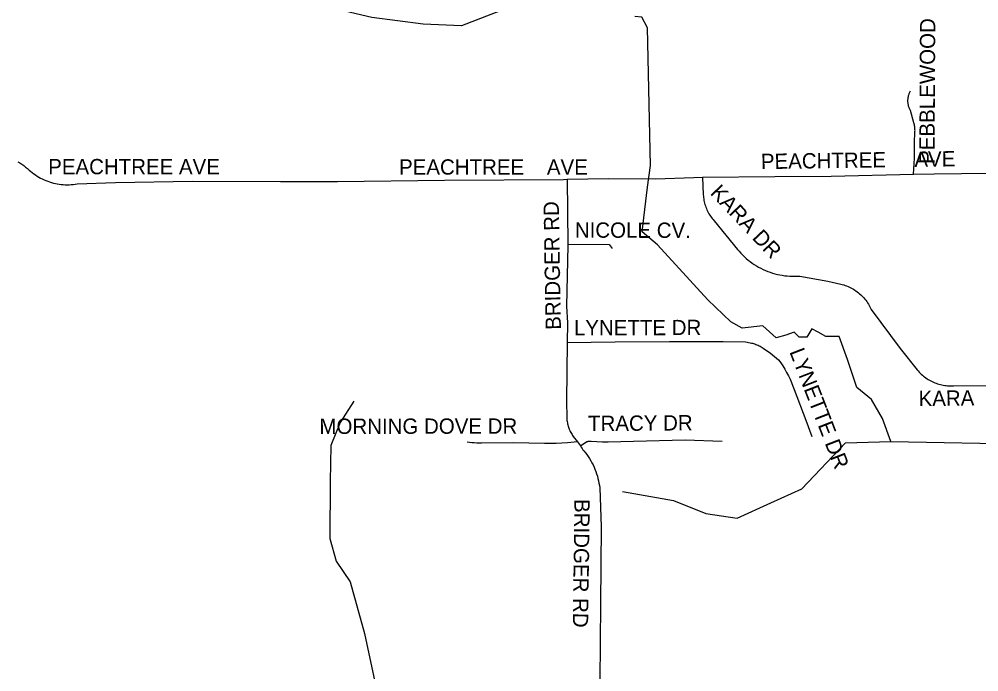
# Model space of a CAD drawing. Extents: x 1670563 to 1761545, y 515755 to 578944.
# Drawn here: x 1715137 to 1719841, y 561545 to 564740 of the extents above; entities that cross this region are included whole.
import ezdxf

# ---------------------------------------------------------------- set-up
doc = ezdxf.new("R2010")
doc.units = 0
for name, color, linetype in [('SHP_LINE', 7, 'Continuous'), ('STREETCL', 7, 'Continuous'), ('STRNAMES', 7, 'Continuous')]:
    doc.layers.add(name, color=color, linetype=linetype)

msp = doc.modelspace()

# ---------------------------------------------------------------- linework, layer by layer
at = {"layer": 'SHP_LINE'}
for points in [[(1717837, 564821), (1717716, 564791), (1717521, 564791), (1717305, 564708), (1717117, 564715), (1716866, 564749), (1716622, 564805), (1716344, 564944), (1716072, 565069), (1715870, 565195), (1715773, 565264), (1715752, 565410), (1715738, 565605), (1715689, 565710)], [(1718190, 563699), (1718216, 563918), (1718231, 564024), (1718216, 564697), (1718189, 564750), (1718155, 564753)], [(1719410, 562672), (1719369, 562785), (1719314, 562878), (1719242, 562936), (1719197, 563073), (1719156, 563186), (1719091, 563186), (1719053, 563207), (1719022, 563224), (1718998, 563183), (1718960, 563183), (1718936, 563207), (1718895, 563193), (1718847, 563180), (1718782, 563238), (1718681, 563227), (1718626, 563259), (1718512, 563366), (1718266, 563635), (1718190, 563699)], [(1716777, 562870), (1716710, 562766), (1716665, 562653), (1716662, 562476), (1716660, 562197), (1716691, 562087), (1716760, 561985), (1716829, 561733), (1716881, 561495)], [(1718095, 562428), (1718344, 562383), (1718502, 562319), (1718657, 562297), (1718822, 562372), (1718973, 562440), (1719187, 562665), (1719410, 562672)], [(1719410, 562672), (1720107, 562660)]]:
    msp.add_lwpolyline(points, dxfattribs=at)
at = {"layer": 'STREETCL'}
for points in [[(1719520.3, 563981), (1719525.1, 564059.7), (1719525.1, 564086.8), (1719525.7, 564135.8), (1719527.7, 564184.8), (1719527.8, 564189.6), (1719527.9, 564194.5), (1719527.7, 564199.3), (1719527.4, 564204.1), (1719527, 564208.9), (1719526.4, 564213.7), (1719525.7, 564218.5), (1719524.8, 564223.2), (1719523.7, 564227.9), (1719522.5, 564232.6), (1719505.7, 564293.2), (1719504.1, 564296.1), (1719502.7, 564299.1), (1719501.3, 564302.1), (1719500, 564305.2), (1719498.9, 564308.3), (1719497.8, 564311.5), (1719496.8, 564314.6), (1719496, 564317.9), (1719495.3, 564321.1), (1719494.7, 564324.4), (1719494.2, 564327.7), (1719493.8, 564331), (1719493.5, 564334.3), (1719493.3, 564337.6), (1719493.2, 564340.9), (1719493.3, 564344.2), (1719493.5, 564347.6), (1719493.8, 564350.9), (1719494.2, 564354.2), (1719494.7, 564357.5), (1719495.3, 564360.7), (1719496, 564364), (1719496.8, 564367.2), (1719497.8, 564370.4), (1719498.9, 564373.5), (1719500, 564376.6), (1719501.3, 564379.7), (1719502.7, 564382.7), (1719504.1, 564385.7), (1719505.7, 564388.7)], [(1715130.6, 564041.9), (1715140.4, 564036), (1715149.9, 564029.7), (1715159.2, 564023.2), (1715168.3, 564016.3), (1715177.2, 564009.1), (1715185.8, 564001.6), (1715193.1, 563995.2), (1715200.7, 563989.1), (1715208.5, 563983.2), (1715216.5, 563977.6), (1715224.7, 563972.3), (1715233, 563967.2), (1715241.6, 563962.5), (1715250.2, 563958.1), (1715259.1, 563953.9), (1715268, 563950.1), (1715277.1, 563946.6), (1715286.4, 563943.3), (1715295.7, 563940.5), (1715305.1, 563937.9), (1715314.6, 563935.7), (1715324.2, 563933.8), (1715333.8, 563932.2), (1715343.5, 563931), (1715353.2, 563930.1), (1715362.9, 563929.5), (1715372.7, 563929.3), (1715382.4, 563929.4), (1715392.2, 563929.9), (1715401.9, 563930.7), (1715411.6, 563931.8), (1715421.2, 563933.3), (1715609.1, 563940.5), (1715986.4, 563947.8), (1716417.4, 563945.4), (1716696.8, 563945.4), (1717222.6, 563952.7), (1717805.3, 563955.8), (1717822.3, 563956.1)], [(1718486.5, 563966.1), (1718841.6, 563970.4), (1719116.2, 563972), (1719520.3, 563981)], [(1719520.3, 563981), (1719621.9, 563983.3), (1720157.1, 563989.8)], [(1717822.3, 563956.1), (1718026.1, 563959.8), (1718255.7, 563959.1), (1718444.3, 563965.5), (1718486.5, 563966.1)], [(1717822.3, 563956.1), (1717826.1, 563638.5)], [(1718486.5, 563966.1), (1718490.3, 563880.8), (1718490.7, 563873.7), (1718491.4, 563866.7), (1718492.3, 563859.7), (1718493.5, 563852.8), (1718494.9, 563845.9), (1718496.6, 563839), (1718498.5, 563832.3), (1718500.6, 563825.5), (1718503, 563818.9), (1718505.6, 563812.4), (1718508.4, 563805.9), (1718511.5, 563799.5), (1718514.7, 563793.3), (1718518.2, 563787.2), (1718521.9, 563781.2), (1718525.8, 563775.3), (1718529.9, 563769.6), (1718534.2, 563764), (1718538.7, 563758.6), (1718543.4, 563753.3), (1718657.7, 563613), (1718665.7, 563603.6), (1718674, 563594.4), (1718682.6, 563585.5), (1718691.5, 563577), (1718700.7, 563568.7), (1718710.1, 563560.8), (1718719.9, 563553.2), (1718729.9, 563545.9), (1718740.1, 563539), (1718750.6, 563532.4), (1718761.3, 563526.3), (1718772.2, 563520.4), (1718783.3, 563515), (1718794.6, 563510), (1718806.1, 563505.3), (1718817.7, 563501.1), (1718829.4, 563497.2), (1718841.3, 563493.8), (1718853.3, 563490.8), (1718865.3, 563488.2), (1718877.5, 563486), (1718889.7, 563484.2), (1718902, 563482.9), (1718914.4, 563481.9), (1718926.7, 563481.5), (1718939.1, 563481.4), (1718951.4, 563481.8), (1718963.7, 563482.6), (1719100.5, 563457.6), (1719164.2, 563442.7), (1719171.4, 563440.9), (1719178.6, 563438.8), (1719185.6, 563436.5), (1719192.6, 563433.9), (1719199.5, 563431.1), (1719206.3, 563428.1), (1719213, 563424.9), (1719219.6, 563421.4), (1719226, 563417.7), (1719232.4, 563413.7), (1719238.6, 563409.6), (1719244.6, 563405.3), (1719250.5, 563400.7), (1719256.2, 563396), (1719261.8, 563391), (1719267.2, 563385.9), (1719272.4, 563380.6), (1719277.4, 563375.1), (1719282.2, 563369.4), (1719286.9, 563363.6), (1719291.3, 563357.6), (1719295.6, 563351.5), (1719299.6, 563345.3), (1719303.4, 563338.9), (1719307, 563332.3), (1719310.3, 563325.7), (1719313.5, 563318.9), (1719455.4, 563127.5), (1719539.3, 563023.2), (1719543.8, 563017.7), (1719548.6, 563012.3), (1719553.6, 563007.1), (1719558.7, 563002.1), (1719564, 562997.3), (1719569.5, 562992.6), (1719575.1, 562988.2), (1719580.9, 562983.9), (1719586.8, 562979.9), (1719592.8, 562976), (1719599, 562972.3), (1719605.3, 562968.9), (1719611.7, 562965.7), (1719618.2, 562962.7), (1719624.9, 562959.9), (1719631.6, 562957.4), (1719638.4, 562955.1), (1719645.2, 562953), (1719652.2, 562951.2), (1719659.2, 562949.6), (1719666.2, 562948.2), (1719673.3, 562947.1), (1719680.4, 562946.3), (1719687.6, 562945.6), (1719694.7, 562945.3), (1719701.9, 562945.1), (1719709.1, 562945.3), (1719716.2, 562945.6), (1720086.9, 562948.2)], [(1717826.1, 563638.5), (1717826.2, 563632.7), (1717819.9, 563334.3), (1717824.1, 563253.1), (1717823, 563156.5)], [(1717826.1, 563638.5), (1718029.2, 563637.2), (1718043.6, 563617.7)], [(1717823, 563156.5), (1717819.9, 562872.1), (1717821.3, 562786.8), (1717821.7, 562781.1), (1717822.2, 562775.5), (1717823, 562769.9), (1717823.9, 562764.3), (1717825.1, 562758.8), (1717826.4, 562753.3), (1717827.9, 562747.9), (1717829.6, 562742.5), (1717831.5, 562737.1), (1717833.6, 562731.9), (1717835.9, 562726.7), (1717838.4, 562721.6), (1717841, 562716.6), (1717843.8, 562711.7), (1717846.8, 562706.9), (1717849.9, 562702.2), (1717853.2, 562697.6), (1717873.6, 562669.9)], [(1717823, 563156.5), (1718058.7, 563161), (1718324.7, 563162.6), (1718587.5, 563162.7), (1718696.3, 563159.9), (1718720.3, 563155.8), (1718725.9, 563154.6), (1718731.5, 563153.2), (1718737, 563151.6), (1718742.4, 563149.9), (1718747.8, 563148), (1718753.2, 563145.9), (1718758.4, 563143.6), (1718763.6, 563141.2), (1718768.7, 563138.6), (1718773.7, 563135.8), (1718778.7, 563132.9), (1718783.5, 563129.8), (1718819.5, 563104.5), (1718858.9, 563072.8), (1718869.7, 563057.8), (1718879.9, 563042.5), (1718889.6, 563026.8), (1718898.8, 563010.8), (1718907.4, 562994.5), (1718915.5, 562977.9), (1718923, 562961.1), (1718929.9, 562944), (1718936.3, 562926.7), (1718992.7, 562777.3), (1719022.6, 562697.3)], [(1717873.6, 562669.9), (1717824.4, 562665.8), (1717796.6, 562663.9), (1717768.6, 562662.7), (1717740.7, 562662.3), (1717712.7, 562662.7), (1717558.1, 562665.2), (1717403.4, 562664), (1717391.5, 562664), (1717379.6, 562664.3), (1717367.7, 562665), (1717355.8, 562666.1), (1717343.9, 562667.5), (1717332.2, 562669.2)], [(1717873.6, 562669.9), (1717887.8, 562650.6)], [(1717887.8, 562650.6), (1717919.5, 562671.5), (1717920.6, 562671.9), (1717921.7, 562672.4), (1717922.8, 562672.8), (1717923.9, 562673.1), (1717925.1, 562673.4), (1717926.2, 562673.7), (1717927.4, 562674), (1717928.6, 562674.1), (1717929.8, 562674.3), (1717931, 562674.4), (1717932.1, 562674.5), (1717933.3, 562674.5), (1717934.5, 562674.5), (1717935.7, 562674.4), (1717936.9, 562674.4), (1717938.1, 562674.2), (1717939.3, 562674), (1717940.5, 562673.8), (1717968.1, 562672), (1717995.7, 562671), (1718023.4, 562671), (1718148.3, 562673.8), (1718401, 562679.8), (1718582.1, 562674.7)], [(1717887.8, 562650.6), (1717891.9, 562644.3), (1717896.2, 562638.2), (1717900.6, 562632.2), (1717905.3, 562626.4), (1717912.7, 562617.3), (1717919.7, 562607.9), (1717926.4, 562598.3), (1717932.7, 562588.4), (1717938.8, 562578.3), (1717944.4, 562568.1), (1717949.8, 562557.6), (1717954.7, 562547), (1717959.3, 562536.2), (1717963.6, 562525.3), (1717967.4, 562514.2), (1717970.9, 562503), (1717974, 562491.7), (1717976.7, 562480.3), (1717979, 562468.8), (1717980.9, 562457.2), (1717982.5, 562445.6), (1717990.1, 562254.7), (1717986.7, 561877.2), (1717982.5, 561498.3)]]:
    msp.add_lwpolyline(points, dxfattribs=at)

# ---------------------------------------------------------------- texts
at = {"layer": 'STRNAMES'}
for s, rotation, p in [('PEBBLEWOOD DR', 89.6929, (1719623.6, 564031.5)), ('PEACHTREE     AVE', 0.8215, (1718773, 564005.9)), ('KARA DR', 313.2349, (1718520.1, 563886.2)), ('BRIDGER RD', 90.9853, (1717792.6, 563219.8)), ('NICOLE CV.', 359.8639, (1717860.7, 563670.3)), ('LYNETTE DR', 0.1411, (1717856.4, 563191.8)), ('LYNETTE DR', 291.1916, (1718911.3, 563112.1)), ('KARA  DR', 0.7064, (1719545.9, 562845.3)), ('MORNING DOVE DR', 0.0721, (1716609, 562709.3)), ('TRACY DR', 0.444, (1717925.7, 562723)), ('BRIDGER RD', 269.2249, (1717859, 562391))]:
    msp.add_text(s, height=75, rotation=rotation, dxfattribs=at).set_placement(p)
for s, p in [('PEACHTREE AVE', (1715279.4, 563980.7)), ('PEACHTREE    AVE', (1716999.1, 563979))]:
    msp.add_text(s, height=75, dxfattribs=at).set_placement(p)

doc.saveas('drawing.dxf')
